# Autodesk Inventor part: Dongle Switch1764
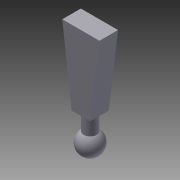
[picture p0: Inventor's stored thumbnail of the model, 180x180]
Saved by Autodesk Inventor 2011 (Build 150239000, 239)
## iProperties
Created: 2010-01
Part Number: Dongle Switch1764
Document SubType Name: Modeling
Designer: jgehrig
Density: 1 g/cm^3
Author: jgehrig
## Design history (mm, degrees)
sketch "Sketch1"
  geometry: L1 (-6.921, 27.03)-(-1.841, 27.03); L2 (-3.111, 16.87)-(-5.651, 16.87); L3 (-6.921, 27.03)-(-5.651, 16.87); L4 (-3.111, 16.87)-(-1.841, 27.03); 1 further point
  constraints: 8 end point, 1 horizontal, 1 parallel
  dimensions: "d0" = 5.08 distance of L1.start L1.end; "d1" = 2.54 distance of L2.start L2.end; "d2" = 10.16 distance between parallel lines of L2 L1; "d3" = 1.27 horizontal distance of L1.start L2.end
extrude "Extrusion1" new body sketch "Sketch1" distance "d4" = 2.54; taper "d5" = 0 deg
workplane "Work Plane1"
sketch "Sketch2"
  geometry: L1 (-3.111, 16.87)-(-5.651, 16.87) reference; L2 (-4.381, 16.87)-(-4.381, 14.33); L3 (-3.492, 16.87)-(-3.492, 14.33); L4 (-4.381, 14.33)-(-3.492, 14.33); L5 (-4.381, 16.87)-(-3.492, 16.87); L6 (-4.381, 14.33)-(-4.381, 11.536); L7 (-4.381, 16.87)-(-3.492, 16.87); L8 (-3.492, 16.87)-(-4.381, 16.87); L9 (-4.381, 16.87)-(-3.492, 16.87); L10 (-3.492, 16.87)-(-3.492, 14.33); L11 (-3.492, 14.33)-(-4.381, 14.33); L12 (-4.381, 14.33)-(-4.381, 16.87); A1 r 1.587 centre (-4.381, 13.124) between (-4.381, 11.536) and (-4.381, 14.711); 1 further point
  constraints: 22 end point, 5 perpendicular, 3 parallel, 2 collinear, 2 point on circle, 2 point on line, 1 centre point, 1 horizontal, 1 midpoint
  dimensions: "d7" = 2.54 distance of L2.start L2.end; "d8" = 0.889 distance of L2.end L3.end; "d9" = 0 distance from line of L6 A1.centre; "d10" = 0.381 distance of A1.end L2.end; "d11" = 3.175 distance of L6.end A1.end
revolve "Revolution1" sketch "Sketch2" stored, may be unused: angle "d12" = 90 deg
body "Solid1"
other parameters: "d6" = 1.27
